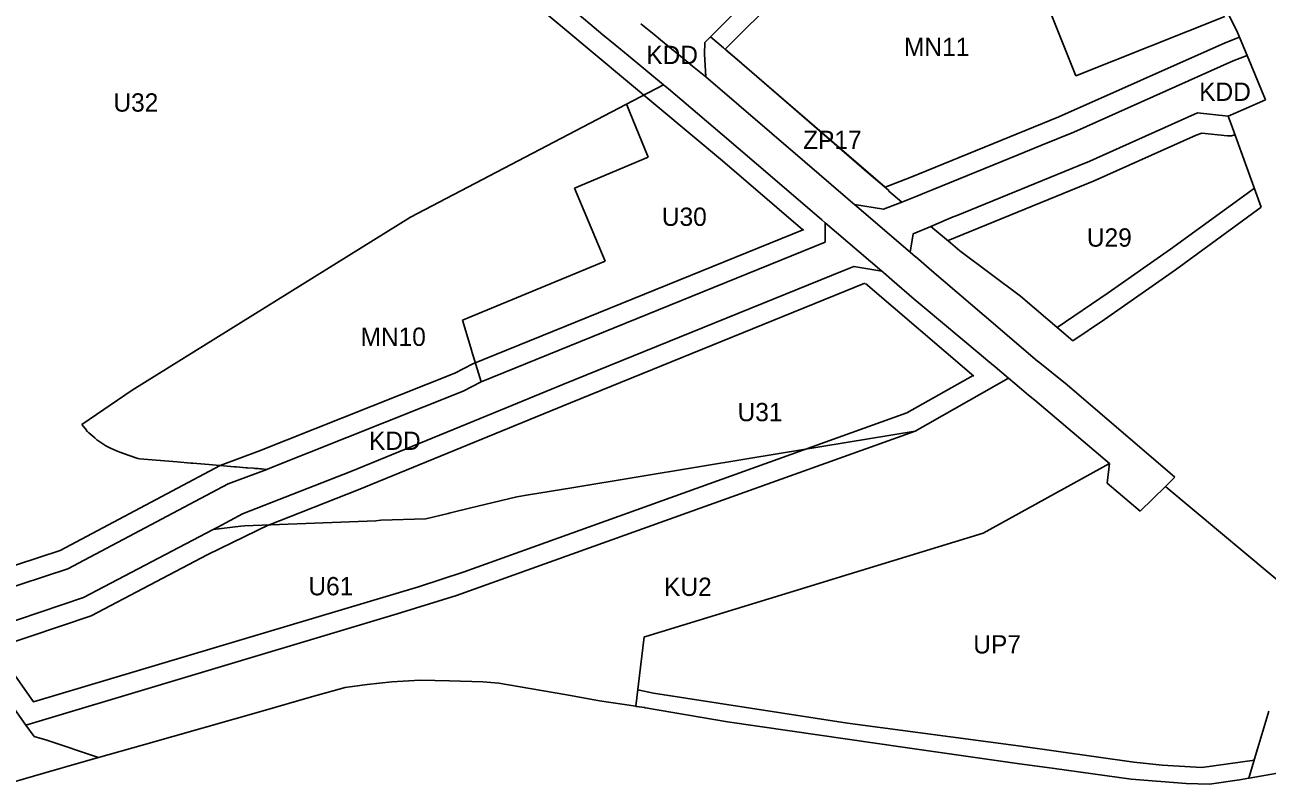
# Model space of a CAD drawing. Extents: x 7428080 to 7432143, y 5545880 to 5549217.
# Drawn here: x 7429638.6 to 7430015.1, y 5547424.9 to 5547654.9 of the extents above; entities that cross this region are included whole.
import ezdxf

# ---------------------------------------------------------------- set-up
doc = ezdxf.new("R2010")
doc.units = 0
for name, color, linetype in [('CZ_L_linie rozgraniczające tereny o różnym przeznaczeniu oraz różnych warunkach ich zabudowy i zagospodarowania', 7, 'Continuous'), ('CZ_L_maksymalne nieprzekraczalne linie zabudowy', 7, 'Continuous'), ('CZ_L_opisy_linie rozgraniczające tereny o różnym przeznaczeniu oraz różnych warunkach ich zabudowy i zagospodarowania', 7, 'Continuous')]:
    doc.layers.add(name, color=color, linetype=linetype)

msp = doc.modelspace()

# ---------------------------------------------------------------- linework, layer by layer
at = {"layer": 'CZ_L_linie rozgraniczające tereny o różnym przeznaczeniu oraz różnych warunkach ich zabudowy i zagospodarowania'}
for p, q in [((7429848.02, 5547652.92), (7429897.36, 5547702.38)), ((7429951.07, 5547654.57), (7429941.9, 5547677.46)), ((7429813.8, 5547651.89), (7429803.97, 5547660.13)), ((7430002.31, 5547657.48), (7429957.13, 5547639.45)), ((7430003.46, 5547657.95), (7430006.08, 5547652.64)), ((7429817.52, 5547648.84), (7429813.8, 5547651.89)), ((7429825.32, 5547655.26), (7429829.31, 5547651.99)), ((7429829.31, 5547651.99), (7429831.25, 5547650.39)), ((7429846.38, 5547651.29), (7429848.02, 5547652.92)), ((7429957.13, 5547639.45), (7429951.07, 5547654.57)), ((7430006.08, 5547652.64), (7430009.02, 5547645.59)), ((7429821.4, 5547645.63), (7429817.52, 5547648.84)), ((7429831.25, 5547650.39), (7429839.03, 5547644.02)), ((7429844.59, 5547646), (7429844.66, 5547649.59)), ((7429844.66, 5547649.59), (7429846.38, 5547651.29)), ((7429848.31, 5547649.69), (7429846.38, 5547651.29)), ((7429850.38, 5547647.92), (7429848.31, 5547649.69)), ((7429832.12, 5547636.75), (7429821.4, 5547645.63)), ((7429844.97, 5547639.15), (7429844.59, 5547646)), ((7429851.39, 5547647.07), (7429850.38, 5547647.92)), ((7429854.41, 5547644.54), (7429851.39, 5547647.07)), ((7429877.81, 5547624.21), (7429854.41, 5547644.54)), ((7430004.82, 5547644.02), (7430009.02, 5547645.59)), ((7430009.02, 5547645.59), (7430014.6, 5547632.22)), ((7429839.03, 5547644.02), (7429840.98, 5547642.42)), ((7429840.98, 5547642.42), (7429844.97, 5547639.15)), ((7429956.49, 5547622.42), (7430004.82, 5547644.02)), ((7429844.97, 5547639.15), (7429874.96, 5547613.46)), ((7429820.78, 5547630.83), (7429832.12, 5547636.75)), ((7429833.63, 5547635.51), (7429832.12, 5547636.75)), ((7429837.72, 5547632.12), (7429833.63, 5547635.51)), ((7429820.78, 5547630.83), (7429755.47, 5547596.67)), ((7429821.07, 5547630.69), (7429820.78, 5547630.83)), ((7429821.89, 5547628.66), (7429821.07, 5547630.69)), ((7429849.92, 5547621.7), (7429837.72, 5547632.12)), ((7430007.96, 5547629.29), (7430003.29, 5547627.24)), ((7430014.6, 5547632.22), (7430007.96, 5547629.29)), ((7429821.88, 5547628.65), (7429821.89, 5547628.66)), ((7429827.49, 5547614.83), (7429821.88, 5547628.65)), ((7429993.98, 5547628.23), (7429960.5, 5547613.26)), ((7430003.27, 5547627.25), (7429993.98, 5547628.23)), ((7430003.27, 5547627.25), (7430004.17, 5547624.85)), ((7430003.29, 5547627.24), (7430003.27, 5547627.25)), ((7429865.21, 5547608.65), (7429849.92, 5547621.7)), ((7429893.8, 5547610.4), (7429877.81, 5547624.21)), ((7429946.53, 5547618.36), (7429956.49, 5547622.42)), ((7430004.17, 5547624.85), (7430013.32, 5547599.69)), ((7429939.61, 5547615.53), (7429946.53, 5547618.36)), ((7429805.13, 5547605.48), (7429827.49, 5547614.83)), ((7429913.92, 5547605.04), (7429939.61, 5547615.53)), ((7429874.96, 5547613.46), (7429887.27, 5547602.82)), ((7429960.35, 5547613.2), (7429920.86, 5547597.07)), ((7429960.41, 5547613.24), (7429960.35, 5547613.2)), ((7429960.5, 5547613.26), (7429960.41, 5547613.24)), ((7429880.1, 5547595.82), (7429865.21, 5547608.65)), ((7429900.37, 5547604.78), (7429893.8, 5547610.4)), ((7429814.46, 5547583.32), (7429805.13, 5547605.48)), ((7429900.43, 5547604.55), (7429900.37, 5547604.78)), ((7429904.39, 5547601.24), (7429900.43, 5547604.55)), ((7429904.39, 5547601.24), (7429908.94, 5547603.01)), ((7429908.94, 5547603.01), (7429911.83, 5547604.18)), ((7429911.83, 5547604.18), (7429913.92, 5547605.04)), ((7429887.27, 5547602.82), (7429887.29, 5547602.82)), ((7429887.29, 5547602.82), (7429887.29, 5547602.81)), ((7429887.29, 5547602.81), (7429889.54, 5547600.89)), ((7429889.54, 5547600.89), (7429890.06, 5547600.44)), ((7429890.06, 5547600.44), (7429898.83, 5547599.08)), ((7429906.91, 5547586.03), (7429890.06, 5547600.44)), ((7429898.83, 5547599.08), (7429904.39, 5547601.24)), ((7430013.32, 5547599.69), (7429987.34, 5547580.68)), ((7429755.47, 5547596.67), (7429671.1, 5547544.2)), ((7429881.15, 5547594.92), (7429880.1, 5547595.82)), ((7429918.55, 5547596.13), (7429913.19, 5547593.87)), ((7429919.23, 5547596.41), (7429918.55, 5547596.13)), ((7429919.97, 5547596.71), (7429919.23, 5547596.41)), ((7429920.86, 5547597.07), (7429919.97, 5547596.71)), ((7429881.2, 5547589.03), (7429881.15, 5547594.92)), ((7429881.15, 5547594.92), (7429898.32, 5547580.24)), ((7429919.12, 5547588.92), (7429913.19, 5547593.87)), ((7429776.87, 5547546.72), (7429881.2, 5547589.03)), ((7429921.97, 5547586.47), (7429919.12, 5547588.92)), ((7429908.57, 5547584.6), (7429906.91, 5547586.03)), ((7429908.57, 5547584.6), (7429908.6, 5547584.6)), ((7429908.6, 5547584.6), (7429912.68, 5547581.12)), ((7429940.31, 5547572.76), (7429921.97, 5547586.47)), ((7429771.2, 5547565.43), (7429814.46, 5547583.32)), ((7429886.78, 5547580.49), (7429801.68, 5547545.93)), ((7429889.87, 5547581.71), (7429886.78, 5547580.49)), ((7429898.32, 5547580.24), (7429889.87, 5547581.71)), ((7429912.68, 5547581.12), (7429912.76, 5547581.06)), ((7429912.76, 5547581.06), (7429912.76, 5547581.04)), ((7429912.76, 5547581.04), (7429933.46, 5547563.35)), ((7429987.34, 5547580.68), (7429965.84, 5547565.62)), ((7429898.78, 5547579.84), (7429898.32, 5547580.24)), ((7429901.36, 5547577.64), (7429898.78, 5547579.84)), ((7429908.15, 5547571.84), (7429901.36, 5547577.64)), ((7429940.33, 5547572.75), (7429940.31, 5547572.76)), ((7429911.12, 5547569.29), (7429908.15, 5547571.84)), ((7429927.83, 5547555.31), (7429911.12, 5547569.29)), ((7429956.22, 5547559.13), (7429940.33, 5547572.75)), ((7429774.05, 5547556.02), (7429771.2, 5547565.43)), ((7429965.8, 5547565.64), (7429956.22, 5547559.13)), ((7429965.84, 5547565.62), (7429965.8, 5547565.64)), ((7429933.46, 5547563.35), (7429933.47, 5547563.35)), ((7429933.47, 5547563.35), (7429945.65, 5547552.95)), ((7429773.99, 5547555.99), (7429774.05, 5547556.02)), ((7429774.08, 5547555.94), (7429773.99, 5547555.99)), ((7429776.87, 5547546.72), (7429774.08, 5547555.94)), ((7429930.5, 5547553.07), (7429927.83, 5547555.31)), ((7429932.64, 5547551.29), (7429930.5, 5547553.07)), ((7429936.72, 5547547.87), (7429932.64, 5547551.29)), ((7429945.65, 5547552.95), (7429945.66, 5547552.94)), ((7429945.66, 5547552.94), (7429954.5, 5547545.81)), ((7429771.41, 5547543.92), (7429776.87, 5547546.72)), ((7429936.72, 5547547.87), (7429908.43, 5547531.85)), ((7429938.62, 5547546.28), (7429936.72, 5547547.87)), ((7429671.1, 5547544.2), (7429655.86, 5547533.81)), ((7429712.37, 5547520.42), (7429771.41, 5547543.92)), ((7429801.68, 5547545.93), (7429784.46, 5547538.88)), ((7429940.65, 5547544.56), (7429938.62, 5547546.28)), ((7429942.77, 5547542.76), (7429940.65, 5547544.56)), ((7429944.67, 5547541.16), (7429942.77, 5547542.76)), ((7429954.5, 5547545.81), (7429987.16, 5547517.92)), ((7429784.46, 5547538.88), (7429772.62, 5547534.04)), ((7429967.3, 5547522.02), (7429944.67, 5547541.16)), ((7429655.86, 5547533.81), (7429657.28, 5547532.1)), ((7429657.28, 5547532.1), (7429657.22, 5547532.06)), ((7429657.22, 5547532.06), (7429657.56, 5547531.7)), ((7429657.56, 5547531.7), (7429657.95, 5547531.3)), ((7429772.62, 5547534.04), (7429737.38, 5547519.61)), ((7429844.63, 5547508.98), (7429908.43, 5547531.85)), ((7429908.43, 5547531.85), (7429858.59, 5547523.59)), ((7429657.95, 5547531.3), (7429659.77, 5547529.74)), ((7429659.77, 5547529.74), (7429660.22, 5547529.36)), ((7429660.22, 5547529.36), (7429660.52, 5547529.1)), ((7429660.52, 5547529.1), (7429660.67, 5547529)), ((7429660.67, 5547529), (7429660.67, 5547529)), ((7429660.67, 5547529), (7429660.69, 5547528.98)), ((7429660.69, 5547528.98), (7429660.71, 5547528.97)), ((7429660.71, 5547528.97), (7429660.75, 5547528.95)), ((7429660.75, 5547528.95), (7429663.14, 5547527.34)), ((7429663.14, 5547527.34), (7429664.53, 5547526.68)), ((7429664.53, 5547526.68), (7429666.38, 5547525.81)), ((7429666.38, 5547525.81), (7429667.42, 5547525.43)), ((7429667.42, 5547525.43), (7429670.23, 5547524.44)), ((7429670.23, 5547524.44), (7429672.84, 5547523.52)), ((7429672.84, 5547523.52), (7429673.37, 5547523.47)), ((7429673.37, 5547523.47), (7429684.79, 5547522.48)), ((7429684.79, 5547522.48), (7429688.86, 5547522.13)), ((7429688.86, 5547522.13), (7429689.49, 5547522.07)), ((7429689.49, 5547522.07), (7429694.35, 5547521.68)), ((7429694.35, 5547521.68), (7429702.08, 5547521.05)), ((7429700.25, 5547515.87), (7429711.94, 5547520.24)), ((7429702.08, 5547521.05), (7429702.66, 5547521)), ((7429702.66, 5547521), (7429705.71, 5547520.75)), ((7429705.71, 5547520.75), (7429706.08, 5547520.72)), ((7429706.08, 5547520.72), (7429707.91, 5547520.57)), ((7429707.91, 5547520.57), (7429708.25, 5547520.54)), ((7429708.25, 5547520.54), (7429709.34, 5547520.45)), ((7429709.34, 5547520.45), (7429709.77, 5547520.42)), ((7429709.77, 5547520.42), (7429710.28, 5547520.38)), ((7429710.28, 5547520.38), (7429711.94, 5547520.24)), ((7429711.94, 5547520.24), (7429712.37, 5547520.42)), ((7429858.59, 5547523.59), (7429824.49, 5547517.94)), ((7429929.06, 5547500.91), (7429967.3, 5547522.02)), ((7429966.61, 5547516.1), (7429967.3, 5547522.02)), ((7429737.38, 5547519.61), (7429704.6, 5547506.74)), ((7429824.49, 5547517.94), (7429804.39, 5547514.65)), ((7429987.16, 5547517.92), (7429984.28, 5547515.07)), ((7429651.63, 5547490.12), (7429700.25, 5547515.87)), ((7429804.39, 5547514.65), (7429791.24, 5547512.5)), ((7429976.64, 5547507.53), (7429966.61, 5547516.1)), ((7429984.28, 5547515.07), (7429976.64, 5547507.53)), ((7429984.28, 5547515.07), (7429985, 5547514.47)), ((7429985, 5547514.47), (7430026.23, 5547479.99)), ((7429769.39, 5547482.02), (7429844.63, 5547508.98)), ((7429787.69, 5547511.92), (7429773.4, 5547508.46)), ((7429791.24, 5547512.5), (7429787.69, 5547511.92)), ((7429704.6, 5547506.74), (7429697.07, 5547502.77)), ((7429760.1, 5547505.26), (7429746.52, 5547504.84)), ((7429766.86, 5547506.89), (7429760.1, 5547505.26)), ((7429767.23, 5547506.98), (7429766.86, 5547506.89)), ((7429767.95, 5547507.15), (7429767.23, 5547506.98)), ((7429773.4, 5547508.46), (7429767.95, 5547507.15)), ((7429695.68, 5547502.05), (7429656.35, 5547481.37)), ((7429695.71, 5547502.05), (7429695.68, 5547502.05)), ((7429704.05, 5547503.04), (7429695.71, 5547502.05)), ((7429697.07, 5547502.77), (7429695.71, 5547502.05)), ((7429705.13, 5547503.17), (7429704.05, 5547503.04)), ((7429744.95, 5547504.69), (7429705.13, 5547503.17)), ((7429746.52, 5547504.84), (7429744.95, 5547504.69)), ((7429883.5, 5547486.97), (7429929.06, 5547500.91)), ((7429618.66, 5547479.36), (7429651.63, 5547490.12)), ((7429875.25, 5547484.44), (7429883.5, 5547486.97)), ((7429826.77, 5547469.61), (7429875.25, 5547484.44)), ((7429656.35, 5547481.37), (7429624.8, 5547470.79)), ((7429751.47, 5547476.47), (7429769.39, 5547482.02)), ((7429681.02, 5547455.35), (7429751.47, 5547476.47)), ((7429825.18, 5547460.27), (7429826.27, 5547469.46)), ((7429826.27, 5547469.46), (7429826.31, 5547469.47)), ((7429826.31, 5547469.47), (7429826.77, 5547469.61)), ((7429624.88, 5547462.46), (7429638.93, 5547442.74)), ((7429823.74, 5547448.45), (7429825.18, 5547460.27)), ((7429749.82, 5547455.87), (7429758.4, 5547456.33)), ((7429758.4, 5547456.33), (7429767.28, 5547456.18)), ((7429767.28, 5547456.18), (7429777.37, 5547455.85)), ((7429638.93, 5547442.74), (7429681.02, 5547455.35)), ((7429725.51, 5547451.27), (7429735.69, 5547454.15)), ((7429735.69, 5547454.15), (7429742.34, 5547455.1)), ((7429742.34, 5547455.1), (7429749.82, 5547455.87)), ((7429777.37, 5547455.85), (7429782.27, 5547455.43)), ((7429782.27, 5547455.43), (7429791.68, 5547453.85)), ((7429791.68, 5547453.85), (7429802.83, 5547451.96)), ((7429710.81, 5547447.12), (7429725.51, 5547451.27)), ((7429802.83, 5547451.96), (7429812.78, 5547450.09)), ((7429812.78, 5547450.09), (7429823.74, 5547448.45)), ((7429674.59, 5547436.8), (7429710.81, 5547447.12)), ((7429824.01, 5547448.41), (7429823.74, 5547448.45)), ((7429826.4, 5547448.05), (7429824.01, 5547448.41)), ((7429826.55, 5547448.01), (7429826.4, 5547448.05)), ((7429826.71, 5547448), (7429826.55, 5547448.01)), ((7429851.59, 5547443.76), (7429826.71, 5547448)), ((7430015.61, 5547446.97), (7430012.28, 5547435.82)), ((7429638.93, 5547442.74), (7429641.42, 5547439.25)), ((7429870.43, 5547441.01), (7429851.59, 5547443.76)), ((7429905.44, 5547435.92), (7429870.43, 5547441.01)), ((7429641.42, 5547439.25), (7429645.27, 5547438.16)), ((7429645.27, 5547438.16), (7429660.92, 5547432.92)), ((7429660.92, 5547432.92), (7429674.59, 5547436.8)), ((7429937.96, 5547431.34), (7429905.44, 5547435.92)), ((7430011.6, 5547433.53), (7430009.54, 5547426.64)), ((7430012.28, 5547435.82), (7430011.6, 5547433.53)), ((7429649.55, 5547429.68), (7429644.37, 5547428.21)), ((7429651.01, 5547430.1), (7429649.55, 5547429.68)), ((7429659.07, 5547432.39), (7429651.01, 5547430.1)), ((7429660.92, 5547432.92), (7429659.07, 5547432.39)), ((7429939.35, 5547431.15), (7429937.96, 5547431.34)), ((7429950.66, 5547429.56), (7429939.35, 5547431.15)), ((7429644.37, 5547428.21), (7429634.96, 5547425.43)), ((7429973.92, 5547426.34), (7429950.66, 5547429.56)), ((7429990.57, 5547425.01), (7429973.92, 5547426.34)), ((7430006.74, 5547426.15), (7429997.66, 5547424.86)), ((7430009.54, 5547426.64), (7430006.74, 5547426.15)), ((7430009.63, 5547426.66), (7430009.54, 5547426.64)), ((7430023.35, 5547429.08), (7430009.63, 5547426.66)), ((7429997.66, 5547424.86), (7429990.57, 5547425.01))]:
    msp.add_line(p, q, dxfattribs=at)
for points in [[(7429913.19, 5547593.87), (7429907.86, 5547591.63), (7429906.91, 5547586.03)], [(7429906.91, 5547586.03), (7429908.57, 5547584.6)]]:
    msp.add_lwpolyline(points, dxfattribs=at)
at = {"layer": 'CZ_L_maksymalne nieprzekraczalne linie zabudowy'}
for points in [[(7429432.98, 5547762.57), (7429443.33, 5547745.41), (7429497.66, 5547658.67), (7429516.16, 5547627.33), (7429593.82, 5547518.3), (7429616.89, 5547485.09), (7429649.28, 5547495.66), (7429697.79, 5547521.36), (7429709.74, 5547525.83), (7429768.93, 5547549.39), (7429774.37, 5547552.18), (7429874.72, 5547592.88)], [(7429834.21, 5547661.77), (7429884.22, 5547711.87), (7429883.54, 5547718.65), (7429905.23, 5547736.82), (7429918.38, 5547708.67), (7429907.44, 5547696.52), (7429900, 5547696.54), (7429850.84, 5547647.53)], [(7429874.37, 5547592.84), (7429850.06, 5547613.69), (7429782.09, 5547670.61), (7429780.21, 5547672.58), (7429776.25, 5547677.47), (7429771.72, 5547683.52), (7429765.98, 5547692.69), (7429761.23, 5547701.6), (7429752.32, 5547717.09)], [(7429850.84, 5547647.53), (7429899.34, 5547605.71), (7429906.95, 5547608.67), (7429952.01, 5547627.07), (7430002.39, 5547649.51), (7430006.72, 5547651.14)], [(7430005.35, 5547621.61), (7430004.3, 5547621.33), (7430003.12, 5547621.25), (7429995.36, 5547622.05), (7429993.61, 5547621.49), (7429962.65, 5547607.66), (7429918.42, 5547589.56)], [(7429951.42, 5547563.25), (7429966.96, 5547573.73), (7429985.78, 5547586.97), (7430011.24, 5547605.41)], [(7429893.19, 5547576.62), (7429803.95, 5547540.37), (7429739.61, 5547514.04), (7429712.44, 5547503.37)], [(7429926.22, 5547548.5), (7429893.4, 5547576.55)], [(7429712.49, 5547503.45), (7429694.08, 5547494.43), (7429658.71, 5547475.84), (7429630.07, 5547466.23), (7429629.97, 5547465.65), (7429641.26, 5547449.8), (7429757.88, 5547484.66), (7429771.7, 5547489.24), (7429905.93, 5547537.32), (7429926.05, 5547548.72)], [(7429824.38, 5547453.4), (7429829.08, 5547452.46), (7429887.87, 5547443.36), (7429940.45, 5547436.38), (7429974.69, 5547431.54), (7429983.31, 5547430.61), (7429995.32, 5547429.93), (7430011.32, 5547432.09)]]:
    msp.add_lwpolyline(points, dxfattribs=at)

# ---------------------------------------------------------------- texts
at = {"layer": 'CZ_L_opisy_linie rozgraniczające tereny o różnym przeznaczeniu oraz różnych warunkach ich zabudowy i zagospodarowania'}
for s, p in [('KDD', (7429826.94, 5547643.04)), ('MN11', (7429905.06, 5547645.45)), ('KDD', (7429994.5, 5547631.88)), ('U32', (7429665.43, 5547628.62)), ('ZP17', (7429874.47, 5547617.28)), ('U30', (7429831.65, 5547594.01)), ('U29', (7429960.47, 5547587.71)), ('MN10', (7429740.32, 5547557.64)), ('U31', (7429854.61, 5547534.82)), ('KDD', (7429742.89, 5547526.14)), ('U61', (7429724.52, 5547482.08)), ('KU2', (7429832.33, 5547481.89)), ('UP7', (7429926.04, 5547464.45))]:
    msp.add_text(s, height=5.549, dxfattribs=at).set_placement(p)

doc.saveas('drawing.dxf')
